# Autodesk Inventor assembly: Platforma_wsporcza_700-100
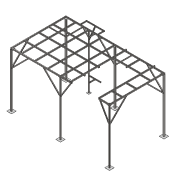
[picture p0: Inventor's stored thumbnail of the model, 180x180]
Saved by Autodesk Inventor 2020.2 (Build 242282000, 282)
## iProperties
Created: 2015-01
Part Number: Platforma_wsporcza_700-100
Document SubType Name: Assembly
Designer: F.Stasiak
Mass: 439812 g
Surface Area: 309977 cm^2
Volume: 75773.9 cm^3
Density: 5.80427 g/cm^3
Description: Platforma wsporcza
Catalog Web Link: www.expertbooks.pl
Manager: www.cadconsulting.pl
Company: Fabian Stasiak CAD Consulting
_SolveAssemblyDoc: Frame Generator Solve Assembly
_Version: 15.0.0
Author: F.Stasiak
Subject: Zbiór ćwiczeń. Autodesk Inventor 2020. Kurs Professional
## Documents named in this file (5)
- C:\2020_Kurs_Professional\R5 RamyMES\Platforma_wsporcza_700-100.iam
- C:\2020_Kurs_Professional\R5 RamyMES\Szkielet_801-800-100.ipt
- C:\2020_Kurs_Professional\R5 RamyMES\Platforma_wsporcza_700-100\Frame\Frame0001.iam
- C:\2020_Kurs_Professional\R5 RamyMES\801-801-101.ipt
- C:\2020_Kurs_Professional\R5 RamyMES\801-801-102.ipt
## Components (15 placed, 4 different names)
1. Szkielet_801-800-100:1
2. Frame0001:1 [sub-assembly] — Zestawiający:1, Równoległy:1, Równoległy:2, Zestawiający:2, Zestawiający:3, Równoległy:3, Zestawiający:4, Zestawiający:5, Zestawiający:6, Zestawiający:7, Zestawiający:8, Zestawiający:9, Zestawiający:10, Zestawiający:11, Zestawiający:12, Zestawiający:13, Równoległy:11, Zestawiający:14, Równoległy:12, Równoległy:13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
3. 801-801-101:1 — Zestawiający:1, Równoległy:1, Równoległy:2
4. 801-801-102:1 — Zestawiający:2, Zestawiający:3, Równoległy:3, Równoległy:5, Równoległy:6, Równoległy:10
5. 801-801-102:2 — Zestawiający:4, Zestawiający:5, Zestawiający:6, Równoległy:4, Równoległy:7
6. 801-801-102:3 — Zestawiający:7, Równoległy:4, Równoległy:5
7. 801-801-102:4 — Zestawiający:8, Równoległy:6, Równoległy:7, Równoległy:8
8. 801-801-102:5 — Zestawiający:9, Równoległy:8, Zestawiający:10, Równoległy:9
9. 801-801-102:6 — Zestawiający:11, Równoległy:9, Równoległy:10
10. 801-801-101:2 — Zestawiający:12, Zestawiający:13, Równoległy:11
11. 801-801-101:3 — Zestawiający:14, Równoległy:12, Równoległy:13, Równoległy:19
12. 801-801-101:4 — Zestawiający:15, Równoległy:14, Równoległy:15
13. 801-801-101:5 — Zestawiający:16, Równoległy:16, Równoległy:17
14. 801-801-101:6 — Zestawiający:17, Równoległy:18, Równoległy:19
15. 801-801-101:7 — Zestawiający:18, Równoległy:20, Równoległy:21
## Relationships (39: Flush 21, Mate 18)
- Zestawiający:1 [Mate]: Frame0001:1 ↔ 801-801-101:1
- Równoległy:1 [Flush]: Frame0001:1 ↔ 801-801-101:1
- Równoległy:2 [Flush]: Frame0001:1 ↔ 801-801-101:1
- Zestawiający:2 [Mate]: Frame0001:1 ↔ 801-801-102:1
- Zestawiający:3 [Mate]: Frame0001:1 ↔ 801-801-102:1
- Równoległy:3 [Flush]: Frame0001:1 ↔ 801-801-102:1
- Zestawiający:4 [Mate]: Frame0001:1 ↔ 801-801-102:2
- Zestawiający:5 [Mate]: Frame0001:1 ↔ 801-801-102:2
- Zestawiający:6 [Mate]: Frame0001:1 ↔ 801-801-102:2
- Zestawiający:7 [Mate]: Frame0001:1 ↔ 801-801-102:3
- Równoległy:4 [Flush]: 801-801-102:2 ↔ 801-801-102:3
- Równoległy:5 [Flush]: 801-801-102:1 ↔ 801-801-102:3
- Zestawiający:8 [Mate]: Frame0001:1 ↔ 801-801-102:4
- Równoległy:6 [Flush]: 801-801-102:1 ↔ 801-801-102:4
- Równoległy:7 [Flush]: 801-801-102:2 ↔ 801-801-102:4
- Zestawiający:9 [Mate]: Frame0001:1 ↔ 801-801-102:5
- Równoległy:8 [Flush]: 801-801-102:4 ↔ 801-801-102:5
- Zestawiający:10 [Mate]: Frame0001:1 ↔ 801-801-102:5
- Zestawiający:11 [Mate]: Frame0001:1 ↔ 801-801-102:6
- Równoległy:9 [Flush]: 801-801-102:5 ↔ 801-801-102:6
- Równoległy:10 [Flush]: 801-801-102:1 ↔ 801-801-102:6
- Zestawiający:12 [Mate]: Frame0001:1 ↔ 801-801-101:2
- Zestawiający:13 [Mate]: Frame0001:1 ↔ 801-801-101:2
- Równoległy:11 [Flush]: Frame0001:1 ↔ 801-801-101:2
- Zestawiający:14 [Mate]: Frame0001:1 ↔ 801-801-101:3
- Równoległy:12 [Flush]: Frame0001:1 ↔ 801-801-101:3
- Równoległy:13 [Flush]: Frame0001:1 ↔ 801-801-101:3
- Zestawiający:15 [Mate]: Frame0001:1 ↔ 801-801-101:4
- Równoległy:14 [Flush]: Frame0001:1 ↔ 801-801-101:4
- Równoległy:15 [Flush]: Frame0001:1 ↔ 801-801-101:4
- Zestawiający:16 [Mate]: Frame0001:1 ↔ 801-801-101:5
- Równoległy:16 [Flush]: Frame0001:1 ↔ 801-801-101:5
- Równoległy:17 [Flush]: Frame0001:1 ↔ 801-801-101:5
- Zestawiający:17 [Mate]: Frame0001:1 ↔ 801-801-101:6
- Równoległy:18 [Flush]: Frame0001:1 ↔ 801-801-101:6
- Równoległy:19 [Flush]: 801-801-101:3 ↔ 801-801-101:6
- Zestawiający:18 [Mate]: Frame0001:1 ↔ 801-801-101:7
- Równoległy:20 [Flush]: Frame0001:1 ↔ 801-801-101:7
- Równoległy:21 [Flush]: Frame0001:1 ↔ 801-801-101:7
